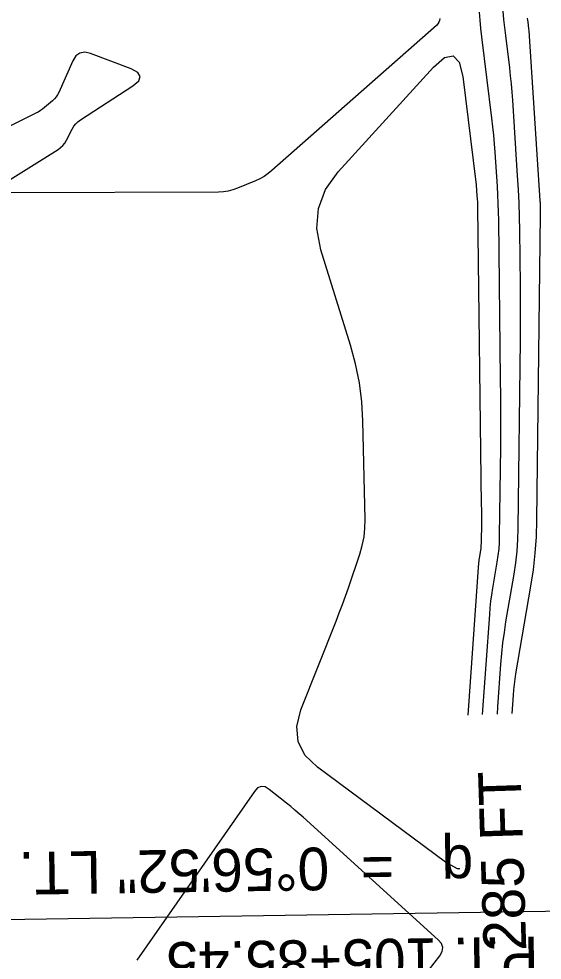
# Model space of a CAD drawing. Extents: x 1768942 to 1774819, y 723037 to 732099.
# Drawn here: x 1770701.2 to 1770774.9, y 724815.1 to 724947.7 of the extents above; entities that cross this region are included whole.
import ezdxf

# ---------------------------------------------------------------- set-up
doc = ezdxf.new("R2010")
doc.units = 0
for name, color, linetype in [('R_Contour Annot', 7, 'Continuous'), ('R_Contours', 7, 'Continuous'), ('R_Horz Alg', 7, 'Continuous'), ('R_Horz Alg Annot', 7, 'Continuous')]:
    doc.layers.add(name, color=color, linetype=linetype)

msp = doc.modelspace()

# ---------------------------------------------------------------- linework, layer by layer
at = {"layer": 'R_Contours'}
for points in [[(1770766.47, 724849.71), (1770767.47, 724863.8), (1770767.54, 724864.73), (1770767.64, 724865.65), (1770767.77, 724866.58), (1770767.91, 724867.5), (1770768.54, 724871.17), (1770768.68, 724872.09), (1770768.78, 724873.02), (1770768.84, 724873.94), (1770768.87, 724874.88), (1770769.02, 724887.36), (1770769.04, 724889.76), (1770769.04, 724892.15), (1770769.04, 724894.54), (1770769.01, 724896.93), (1770768.73, 724919.26), (1770768.71, 724920.46), (1770768.67, 724921.67), (1770768.62, 724922.87), (1770768.55, 724924.07), (1770768.23, 724928.87), (1770768.15, 724930.07), (1770768.04, 724931.27), (1770767.92, 724932.46), (1770767.78, 724933.66), (1770766.37, 724945.12), (1770766.23, 724946.28), (1770766.11, 724947.44), (1770766.01, 724948.6)], [(1770768.56, 724849.77), (1770768.62, 724850.81), (1770769.05, 724856.81), (1770769.17, 724858.3), (1770769.33, 724859.79), (1770769.53, 724861.28), (1770769.76, 724862.76), (1770770.91, 724869.48), (1770771.15, 724871.09), (1770771.33, 724872.71), (1770771.44, 724874.34), (1770771.49, 724875.97), (1770771.8, 724902.43), (1770771.82, 724904.36), (1770771.82, 724906.28), (1770771.82, 724908.21), (1770771.8, 724910.14), (1770771.7, 724917.85), (1770771.66, 724919.77), (1770771.6, 724921.7), (1770771.51, 724923.62), (1770771.4, 724925.55), (1770770.71, 724936.21), (1770770.63, 724937.35), (1770770.53, 724938.49), (1770770.41, 724939.63), (1770770.28, 724940.77), (1770769.72, 724945.31), (1770769.59, 724946.45), (1770769.47, 724947.58), (1770769.37, 724948.72)], [(1770760.43, 724947.7), (1770760.39, 724947.42), (1770760.3, 724947.16), (1770760.16, 724946.93), (1770759.96, 724946.73), (1770736.81, 724926.29), (1770736.27, 724925.86), (1770735.71, 724925.47), (1770735.12, 724925.14), (1770734.5, 724924.85), (1770731.94, 724923.8), (1770731.3, 724923.57), (1770730.64, 724923.4), (1770729.97, 724923.3), (1770729.29, 724923.26), (1770700.04, 724923.15)], [(1770770.63, 724849.84), (1770770.81, 724852.44), (1770770.88, 724853.19), (1770770.96, 724853.94), (1770771.06, 724854.68), (1770771.17, 724855.43), (1770773.28, 724867.78), (1770773.62, 724870.09), (1770773.88, 724872.41), (1770774.04, 724874.74), (1770774.12, 724877.07), (1770774.62, 724920.09), (1770774.62, 724920.25), (1770774.62, 724920.42), (1770774.62, 724920.58), (1770774.62, 724920.75), (1770774.61, 724921.41), (1770774.6, 724921.57), (1770774.6, 724921.73), (1770774.59, 724921.9), (1770774.58, 724922.06), (1770773.08, 724945.22), (1770773.06, 724945.47), (1770773.04, 724945.72), (1770773.01, 724945.97), (1770772.99, 724946.22), (1770772.86, 724947.23), (1770772.83, 724947.48), (1770772.81, 724947.73)], [(1770699.56, 724924.79), (1770706.7, 724929.27), (1770707.05, 724929.53), (1770707.37, 724929.83), (1770707.64, 724930.17), (1770707.86, 724930.55), (1770708.68, 724932.14), (1770708.9, 724932.52), (1770709.17, 724932.86), (1770709.48, 724933.16), (1770709.84, 724933.43), (1770717.22, 724938.22), (1770718.04, 724938.91), (1770718.27, 724939.54), (1770717.91, 724940.1), (1770716.96, 724940.6), (1770711.26, 724942.76), (1770710.45, 724942.94), (1770709.76, 724942.83), (1770709.2, 724942.42), (1770708.75, 724941.72), (1770706.78, 724937.28), (1770706.61, 724936.95), (1770706.41, 724936.65), (1770706.18, 724936.37), (1770705.91, 724936.12), (1770704.79, 724935.17), (1770704.5, 724934.94), (1770704.2, 724934.73), (1770703.88, 724934.53), (1770703.56, 724934.36), (1770695.85, 724930.57)], [(1770763.26, 724827.99), (1770762.93, 724827.99), (1770761.26, 724828.94), (1770743.2, 724842.3), (1770741.45, 724843.99), (1770740.49, 724845.9), (1770740.3, 724848.03), (1770740.89, 724850.39), (1770745.84, 724862.85), (1770746.29, 724864.01), (1770746.74, 724865.19), (1770747.16, 724866.37), (1770747.57, 724867.55), (1770749.18, 724872.3), (1770749.53, 724873.5), (1770749.77, 724874.71), (1770749.9, 724875.94), (1770749.93, 724877.19), (1770749.6, 724891.04), (1770749.45, 724893.75), (1770749.11, 724896.43), (1770748.58, 724899.08), (1770747.86, 724901.7), (1770743.71, 724915.11), (1770743.14, 724918.13), (1770743.36, 724920.97), (1770744.36, 724923.64), (1770746.15, 724926.13), (1770759.54, 724940.86), (1770761.11, 724942.23), (1770762.32, 724942.46), (1770763.18, 724941.57), (1770763.68, 724939.55), (1770765.52, 724924.64), (1770765.55, 724924.34), (1770765.58, 724924.04), (1770765.61, 724923.74), (1770765.63, 724923.44), (1770765.71, 724922.24), (1770765.73, 724921.93), (1770765.74, 724921.63), (1770765.75, 724921.33), (1770765.76, 724921.03), (1770766.28, 724879.19), (1770766.29, 724878.6), (1770766.29, 724878.02), (1770766.29, 724877.43), (1770766.29, 724876.84), (1770766.25, 724873.78), (1770766.24, 724873.55), (1770766.23, 724873.32), (1770766.2, 724873.09), (1770766.17, 724872.87), (1770766.01, 724871.97), (1770765.98, 724871.74), (1770765.95, 724871.51), (1770765.92, 724871.29), (1770765.91, 724871.06), (1770764.39, 724849.64)], [(1770758.04, 724812.65), (1770760.43, 724815.73), (1770760.78, 724816.33), (1770760.86, 724816.91), (1770760.68, 724817.46), (1770760.23, 724817.99), (1770741.2, 724835.24), (1770740.63, 724835.75), (1770740.04, 724836.26), (1770739.45, 724836.76), (1770738.85, 724837.24), (1770736.43, 724839.18), (1770735.84, 724839.52), (1770735.3, 724839.58), (1770734.79, 724839.37), (1770734.33, 724838.87), (1770717.78, 724815.12)]]:
    msp.add_lwpolyline(points, dxfattribs=at)
at = {"layer": 'R_Horz Alg'}
msp.add_lwpolyline([(1770821.12, 724822.68), (1770656.14, 724820.14)], dxfattribs=at)

# ---------------------------------------------------------------- texts
at = {"layer": 'R_Contour Annot'}
msp.add_text('285 FT', height=6, rotation=91.8409, dxfattribs=at).set_placement((1770772.63, 724816.46))
at = {"layer": 'R_Horz Alg Annot'}
for s, p in [('q   =  0%%d56\'52" LT.', (1770765.11, 724831.32)), ('P.I. 105+85.45', (1770774.31, 724818.46))]:
    msp.add_text(s, height=6, rotation=180.8827, dxfattribs=at).set_placement(p)

doc.saveas('drawing.dxf')
